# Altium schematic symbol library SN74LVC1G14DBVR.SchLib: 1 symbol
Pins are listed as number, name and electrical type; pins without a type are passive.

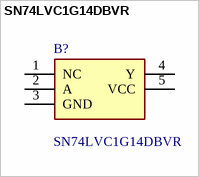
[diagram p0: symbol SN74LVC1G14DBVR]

## SN74LVC1G14DBVR
designator B?
TEXAS INSTRUMENTS - SN74LVC1G14DBVR - IC, SCHMITT TRIGGER INVERTER, SMD; Geometry.Height: 1.45mm
footprint SOT95P280X145-5N
pins: 1 NC, 2 A, 3 GND, 4 Y, 5 VCC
